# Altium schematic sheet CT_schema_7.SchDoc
size 287 x 160 mm
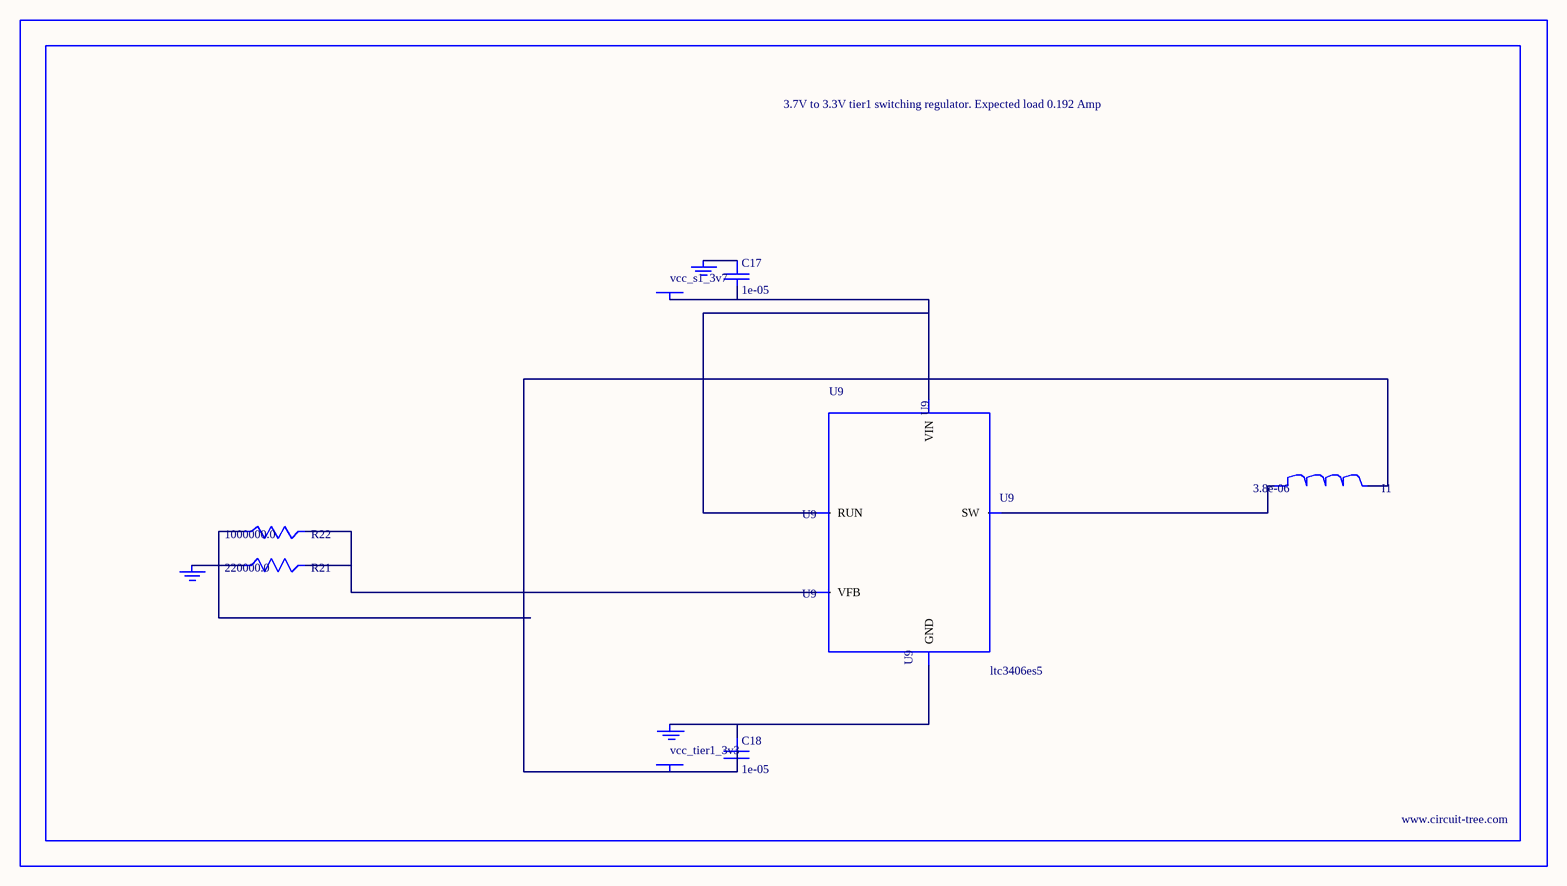
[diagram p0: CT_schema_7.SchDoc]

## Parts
BORDER6  (no value)
C17  1e-05  [C0805]
C18  1e-05  [C0805]
GND_INSTANCE_6_0  (no value)
GND_INSTANCE_6_1  (no value)
GND_INSTANCE_6_2  (no value)
I1  3.8e-06  [DR1040]
POWER_INSTANCE_6_0  vcc_tier1_3v3
POWER_INSTANCE_6_1  vcc_s1_3v7
R21  220000.0  [R0603]
R22  1000000.0  [R0603]
U9  ltc3406es5  [TSOT-23-5]

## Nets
NetC17_1: C17.1 GND_INSTANCE_6_1.0(GND)
NetC17_2: C17.2 POWER_INSTANCE_6_1.0(PWR) U9.1(RUN) U9.4(VIN)
NetC18_1: C18.1 GND_INSTANCE_6_0.0(GND) U9.2(GND)
NetC18_2: C18.2 I1.2 POWER_INSTANCE_6_0.0(PWR) R22.1
NetGND_INSTANCE_6_2_0: GND_INSTANCE_6_2.0(GND) R21.1
NetI1_1: I1.1 U9.3(SW)
NetR21_2: R21.2 R22.2 U9.5(VFB)

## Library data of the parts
BORDER6 = BORDER_PAGE6
C17 C18 = C0805C106K8RACTU
GND_INSTANCE_6_0-GND_INSTANCE_6_2 = GND
I1 = DR1040-3R8-R
POWER_INSTANCE_6_0 POWER_INSTANCE_6_1 = PWR
R21 = RC0603JR-07220KL
R22 = RC0603JR-071ML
